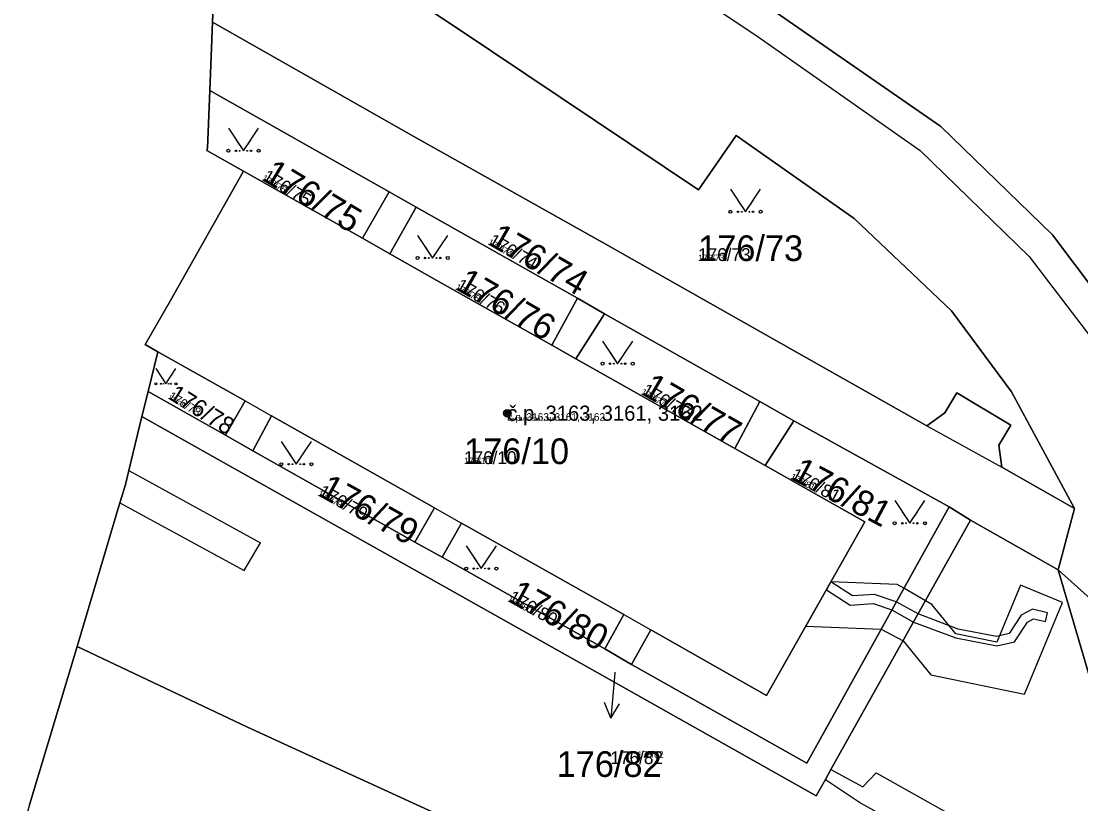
# Model space of a CAD drawing. Extents: x -759873 to -758487, y -975024 to -973516.
# Drawn here: x -759794.5 to -759724.3, y -974881.1 to -974829.3 of the extents above; entities that cross this region are included whole.
import ezdxf

# ---------------------------------------------------------------- set-up
doc = ezdxf.new("R2010")
doc.units = 0
for name, color, linetype in [('KAT_01_hranice KU', 7, 'Continuous'), ('KAT_02_hranice parcel', 7, 'Continuous'), ('KAT_03_1000_st čísla parcelní', 7, 'Continuous'), ('KAT_03_1000_čísla parcelní', 7, 'Continuous'), ('KAT_03_1000_čísla popisná', 7, 'Continuous'), ('KAT_03_250_st čísla parcelní', 7, 'Continuous'), ('KAT_03_250_čísla parcelní', 7, 'Continuous'), ('KAT_03_250_čísla popisná', 7, 'Continuous'), ('KAT_03_500_st čísla parcelní', 7, 'Continuous'), ('KAT_03_500_čísla parcelní', 7, 'Continuous'), ('KAT_03_500_čísla popisná', 7, 'Continuous'), ('KAT_04_vnitřní kresba', 7, 'Continuous'), ('KAT_05_1000_značky kultur', 7, 'Continuous'), ('KAT_05_250_značky kultur', 7, 'Continuous'), ('KAT_05_500_značky kultur', 7, 'Continuous'), ('KAT_07_1000_značky budov', 7, 'Continuous'), ('KAT_07_250_značky budov', 7, 'Continuous'), ('KAT_07_500_značky budov', 7, 'Continuous'), ('KAT_10_věcná břemena', 7, 'Continuous'), ('KAT_12_pomocná šipka', 7, 'Continuous'), ('KAT_14_plocha_budovy', 7, 'Continuous'), ('KAT_14_plocha_pozemek', 7, 'Continuous')]:
    doc.layers.add(name, color=color, linetype=linetype)

msp = doc.modelspace()

# ---------------------------------------------------------------- linework, layer by layer
at = {"layer": 'KAT_01_hranice KU'}
msp.add_lwpolyline([(-759781.42, -974819.34), (-759781.82, -974829.36), (-759782, -974833.89), (-759782.16, -974837.71), (-759782.2, -974837.87), (-759779.77, -974839.24), (-759784.62, -974847.8), (-759786.28, -974850.73), (-759785.45, -974851.2), (-759786.09, -974853.83), (-759786.5, -974855.48), (-759787.37, -974859.06), (-759787.62, -974860.09), (-759787.96, -974861.21), (-759790.8, -974870.73), (-759793.94, -974881.22)], dxfattribs=at)
at = {"layer": 'KAT_02_hranice parcel'}
for p, q in [((-759781.82, -974829.36), (-759781.42, -974819.34)), ((-759782, -974833.89), (-759781.82, -974829.36)), ((-759782, -974833.89), (-759770.13, -974840.61)), ((-759779.77, -974839.24), (-759782.2, -974837.87)), ((-759768.35, -974841.63), (-759770.13, -974840.61)), ((-759768.35, -974841.63), (-759757.65, -974847.65)), ((-759755.88, -974848.68), (-759757.65, -974847.65)), ((-759755.88, -974848.68), (-759745.58, -974854.5)), ((-759785.45, -974851.2), (-759786.28, -974850.73)), ((-759786.09, -974853.83), (-759785.45, -974851.2)), ((-759786.5, -974855.48), (-759786.09, -974853.83)), ((-759786.09, -974853.83), (-759780.96, -974856.72)), ((-759743.32, -974855.78), (-759745.58, -974854.5)), ((-759743.32, -974855.78), (-759733.05, -974861.48)), ((-759780.96, -974856.72), (-759779.17, -974857.76)), ((-759779.17, -974857.76), (-759768.43, -974863.81)), ((-759790.8, -974870.73), (-759787.96, -974861.21)), ((-759733.05, -974861.48), (-759731.62, -974862.36)), ((-759725.83, -974865.65), (-759724.75, -974861.59)), ((-759731.62, -974862.36), (-759725.83, -974865.65)), ((-759768.43, -974863.81), (-759766.63, -974864.81)), ((-759766.63, -974864.81), (-759755.84, -974870.88)), ((-759793.94, -974881.22), (-759790.8, -974870.73)), ((-759755.84, -974870.88), (-759754.08, -974871.91))]:
    msp.add_line(p, q, dxfattribs=at)
for points in [[(-759724.75, -974861.59), (-759728.92, -974853.85), (-759732.89, -974848.49), (-759739.33, -974842.38), (-759747.14, -974836.88), (-759749.64, -974840.47), (-759765.62, -974829.77), (-759781.42, -974819.34)], [(-759720.36, -974851.23), (-759726.2, -974843.46), (-759733.59, -974836.28), (-759747.09, -974826.92)], [(-759781.82, -974829.36), (-759768.49, -974836.95), (-759755.87, -974844.03), (-759743.5, -974851.03), (-759734.53, -974856.1), (-759733.33, -974855.25), (-759732.53, -974853.92), (-759728.96, -974856.06), (-759729.76, -974857.39), (-759729.55, -974858.85), (-759724.75, -974861.59)], [(-759782.2, -974837.87), (-759782.16, -974837.71), (-759782, -974833.89)], [(-759786.28, -974850.73), (-759784.62, -974847.8), (-759779.77, -974839.24)], [(-759770.13, -974840.61), (-759771.9, -974843.68), (-759779.77, -974839.24)], [(-759757.65, -974847.65), (-759759.35, -974850.77), (-759766.97, -974846.48), (-759770.08, -974844.71), (-759768.35, -974841.63)], [(-759745.58, -974854.5), (-759747.24, -974857.61), (-759754.44, -974853.55), (-759757.77, -974851.66), (-759755.88, -974848.68)], [(-759785.45, -974851.2), (-759779.66, -974854.46), (-759780.96, -974856.72)], [(-759787.96, -974861.21), (-759787.62, -974860.09), (-759787.37, -974859.06), (-759786.5, -974855.48)], [(-759786.5, -974855.48), (-759781.8, -974858.13), (-759756.7, -974872.25), (-759741.85, -974880.62), (-759741.24, -974879.53), (-759740.87, -974878.88), (-759731.62, -974862.36)], [(-759779.17, -974857.76), (-759777.92, -974855.45), (-759767.13, -974861.54), (-759768.43, -974863.81)], [(-759754.08, -974871.91), (-759752.8, -974869.63), (-759745.13, -974873.96), (-759738.62, -974862.47), (-759745.23, -974858.74), (-759743.32, -974855.78)], [(-759754.08, -974871.91), (-759742.48, -974878.45), (-759733.05, -974861.48)], [(-759766.63, -974864.81), (-759765.33, -974862.56), (-759754.6, -974868.61), (-759755.84, -974870.88)], [(-759726.65, -974903.86), (-759722.01, -974906.18), (-759718.12, -974905.68), (-759715.36, -974903.46), (-759715.21, -974901.51), (-759717.33, -974894.35), (-759721.59, -974880.08), (-759725.83, -974865.65)], [(-759790.8, -974870.73), (-759779.51, -974876.07), (-759763.52, -974883.39), (-759745.63, -974891.96), (-759725.52, -974901.55), (-759726.65, -974903.86)]]:
    msp.add_lwpolyline(points, dxfattribs=at)
at = {"layer": 'KAT_03_1000_čísla popisná'}
msp.add_circle((-759762.3, -974855.27), 0.25, dxfattribs=at)
at = {"layer": 'KAT_03_250_čísla popisná'}
msp.add_circle((-759762.3, -974855.27), 0.0625, dxfattribs=at)
at = {"layer": 'KAT_03_500_čísla popisná'}
msp.add_circle((-759762.3, -974855.27), 0.125, dxfattribs=at)
at = {"layer": 'KAT_04_vnitřní kresba'}
for p, q in [((-759759.54, -974821.08), (-759745.85, -974830.23)), ((-759745.85, -974830.23), (-759734.96, -974837.86)), ((-759734.96, -974837.86), (-759727.75, -974844.9)), ((-759771.9, -974843.68), (-759770.08, -974844.71)), ((-759727.75, -974844.9), (-759723.04, -974851.05)), ((-759759.35, -974850.77), (-759757.77, -974851.66)), ((-759779.66, -974854.46), (-759777.92, -974855.45)), ((-759734.53, -974856.1), (-759729.55, -974858.85)), ((-759747.24, -974857.61), (-759745.23, -974858.74)), ((-759787.37, -974859.06), (-759778.66, -974863.85)), ((-759787.96, -974861.21), (-759779.74, -974865.7)), ((-759767.13, -974861.54), (-759765.33, -974862.56)), ((-759779.74, -974865.7), (-759778.66, -974863.85)), ((-759725.83, -974865.65), (-759723.69, -974867.57)), ((-759754.6, -974868.61), (-759752.8, -974869.63)), ((-759740.87, -974878.88), (-759738.75, -974880.03)), ((-759737.88, -974879.09), (-759738.75, -974880.03)), ((-759737.88, -974879.09), (-759729.98, -974883.52)), ((-759741.24, -974879.53), (-759738.86, -974881.13)), ((-759738.86, -974881.13), (-759731.02, -974885.44))]:
    msp.add_line(p, q, dxfattribs=at)
at = {"layer": 'KAT_05_1000_značky kultur'}
for points in [[(-759780.78, -974836.389), (-759779.78, -974837.89), (-759778.78, -974836.389)], [(-759747.53, -974840.429), (-759746.53, -974841.93), (-759745.53, -974840.429)], [(-759768.25, -974843.489), (-759767.25, -974844.99), (-759766.25, -974843.489)], [(-759756, -974850.489), (-759755, -974851.99), (-759754, -974850.489)], [(-759785.59, -974852.314), (-759784.92, -974853.32), (-759784.25, -974852.314)], [(-759777.28, -974857.149), (-759776.28, -974858.65), (-759775.28, -974857.149)], [(-759736.65, -974861.059), (-759735.65, -974862.56), (-759734.65, -974861.059)], [(-759765.03, -974864.059), (-759764.03, -974865.56), (-759763.03, -974864.059)]]:
    msp.add_lwpolyline(points, dxfattribs=at)
for centre, radius in [((-759780.78, -974837.889), 0.1), ((-759778.78, -974837.889), 0.1), ((-759747.53, -974841.929), 0.1), ((-759745.53, -974841.929), 0.1), ((-759768.25, -974844.989), 0.1), ((-759766.25, -974844.989), 0.1), ((-759756, -974851.989), 0.1), ((-759754, -974851.989), 0.1), ((-759785.59, -974853.32), 0.067), ((-759784.25, -974853.32), 0.067), ((-759777.28, -974858.649), 0.1), ((-759775.28, -974858.649), 0.1), ((-759736.65, -974862.559), 0.1), ((-759734.65, -974862.559), 0.1), ((-759765.03, -974865.559), 0.1), ((-759763.03, -974865.559), 0.1)]:
    msp.add_circle(centre, radius, dxfattribs=at)
at = {"layer": 'KAT_05_250_značky kultur'}
for points in [[(-759780.03, -974837.515), (-759779.78, -974837.89), (-759779.53, -974837.515)], [(-759746.78, -974841.555), (-759746.53, -974841.93), (-759746.28, -974841.555)], [(-759767.5, -974844.615), (-759767.25, -974844.99), (-759767, -974844.615)], [(-759755.25, -974851.615), (-759755, -974851.99), (-759754.75, -974851.615)], [(-759785.088, -974853.069), (-759784.92, -974853.32), (-759784.753, -974853.069)], [(-759776.53, -974858.275), (-759776.28, -974858.65), (-759776.03, -974858.275)], [(-759735.9, -974862.185), (-759735.65, -974862.56), (-759735.4, -974862.185)], [(-759764.28, -974865.185), (-759764.03, -974865.56), (-759763.78, -974865.185)]]:
    msp.add_lwpolyline(points, dxfattribs=at)
for centre, radius in [((-759780.03, -974837.89), 0.025), ((-759779.53, -974837.89), 0.025), ((-759746.78, -974841.93), 0.025), ((-759746.28, -974841.93), 0.025), ((-759767.5, -974844.99), 0.025), ((-759767, -974844.99), 0.025), ((-759755.25, -974851.99), 0.025), ((-759754.75, -974851.99), 0.025), ((-759785.088, -974853.32), 0.0168), ((-759784.753, -974853.32), 0.0168), ((-759776.53, -974858.65), 0.025), ((-759776.03, -974858.65), 0.025), ((-759735.9, -974862.56), 0.025), ((-759735.4, -974862.56), 0.025), ((-759764.28, -974865.56), 0.025), ((-759763.78, -974865.56), 0.025)]:
    msp.add_circle(centre, radius, dxfattribs=at)
at = {"layer": 'KAT_05_500_značky kultur'}
for points in [[(-759780.28, -974837.14), (-759779.78, -974837.89), (-759779.28, -974837.14)], [(-759747.03, -974841.179), (-759746.53, -974841.93), (-759746.03, -974841.179)], [(-759767.75, -974844.24), (-759767.25, -974844.99), (-759766.75, -974844.24)], [(-759755.5, -974851.24), (-759755, -974851.99), (-759754.5, -974851.24)], [(-759785.255, -974852.817), (-759784.92, -974853.32), (-759784.585, -974852.817)], [(-759776.78, -974857.9), (-759776.28, -974858.65), (-759775.78, -974857.9)], [(-759736.15, -974861.809), (-759735.65, -974862.56), (-759735.15, -974861.809)], [(-759764.53, -974864.809), (-759764.03, -974865.56), (-759763.53, -974864.809)]]:
    msp.add_lwpolyline(points, dxfattribs=at)
for centre, radius in [((-759780.28, -974837.89), 0.05), ((-759779.28, -974837.89), 0.05), ((-759747.03, -974841.93), 0.05), ((-759746.03, -974841.93), 0.05), ((-759767.75, -974844.99), 0.05), ((-759766.75, -974844.99), 0.05), ((-759755.5, -974851.99), 0.05), ((-759754.5, -974851.99), 0.05), ((-759785.255, -974853.32), 0.0335), ((-759784.585, -974853.32), 0.0335), ((-759776.78, -974858.65), 0.05), ((-759775.78, -974858.65), 0.05), ((-759736.15, -974862.56), 0.05), ((-759735.15, -974862.56), 0.05), ((-759764.53, -974865.56), 0.05), ((-759763.53, -974865.56), 0.05)]:
    msp.add_circle(centre, radius, dxfattribs=at)
at = {"layer": 'KAT_07_1000_značky budov'}
msp.add_circle((-759762.307, -974855.269), 0.175, dxfattribs=at)
at = {"layer": 'KAT_07_250_značky budov'}
msp.add_circle((-759762.302, -974855.27), 0.0437, dxfattribs=at)
at = {"layer": 'KAT_07_500_značky budov'}
msp.add_circle((-759762.303, -974855.27), 0.0875, dxfattribs=at)
at = {"layer": 'KAT_10_věcná břemena'}
for points in [[(-759740.87, -974866.44), (-759742.53, -974869.38), (-759737.54, -974869.57), (-759736.09, -974870.35), (-759734.25, -974872.6), (-759728.06, -974873.88), (-759725.54, -974867.82), (-759728.31, -974866.67), (-759729.88, -974870.44), (-759732.61, -974869.88), (-759734.19, -974867.94), (-759734.61, -974867.7), (-759736.04, -974866.86), (-759736.48, -974866.61)], [(-759740.87, -974866.45), (-759741.17, -974866.97), (-759739.61, -974867.98), (-759738.07, -974867.88), (-759736.84, -974868.3), (-759735.4, -974869.11), (-759732.61, -974870.15), (-759729.88, -974870.68), (-759728.72, -974870.41), (-759727.86, -974869.11), (-759727.45, -974868.9), (-759726.67, -974869.07), (-759726.53, -974868.49), (-759727.53, -974868.26), (-759728.28, -974868.65), (-759729.08, -974869.87), (-759729.9, -974870.06), (-759732.45, -974869.57), (-759735.09, -974868.56), (-759736.55, -974867.77), (-759737.99, -974867.28), (-759739.45, -974867.36)]]:
    msp.add_lwpolyline(points, close=True, dxfattribs=at)
at = {"layer": 'KAT_12_pomocná šipka'}
for p, q in [((-759755.19, -974872.49), (-759755.452, -974875.48)), ((-759755.18, -974872.42), (-759755.19, -974872.49)), ((-759755.452, -974875.48), (-759755.863, -974874.438)), ((-759755.452, -974875.48), (-759754.865, -974874.526))]:
    msp.add_line(p, q, dxfattribs=at)
at = {"layer": 'KAT_14_plocha_budovy'}
msp.add_lwpolyline([(-759765.33, -974862.56), (-759754.6, -974868.61), (-759752.8, -974869.63), (-759745.13, -974873.96), (-759738.62, -974862.47), (-759745.23, -974858.74), (-759747.24, -974857.61), (-759754.44, -974853.55), (-759757.77, -974851.66), (-759759.35, -974850.77), (-759766.97, -974846.48), (-759770.08, -974844.71), (-759771.9, -974843.68), (-759779.77, -974839.24), (-759784.62, -974847.8), (-759786.28, -974850.73), (-759785.45, -974851.2), (-759779.66, -974854.46), (-759777.92, -974855.45), (-759767.13, -974861.54)], close=True, dxfattribs=at)
at = {"layer": 'KAT_14_plocha_pozemek'}
for points in [[(-759779.06, -974769.72), (-759779.44, -974777.04), (-759772.97, -974781.39), (-759761.49, -974788.95), (-759760.72, -974789.46), (-759745.11, -974799.84), (-759733.13, -974807.82), (-759734.33, -974809.6), (-759736.06, -974812.44), (-759729.75, -974816.63), (-759737.09, -974827.63), (-759744.46, -974822.74), (-759747.09, -974826.92), (-759733.59, -974836.28), (-759726.2, -974843.46), (-759720.36, -974851.23), (-759711.23, -974851.62), (-759701.47, -974851.98), (-759697.34, -974852.13), (-759694.68, -974852.23), (-759679.76, -974852.8), (-759656.08, -974853.68)], [(-759720.36, -974851.23), (-759726.2, -974843.46), (-759733.59, -974836.28), (-759747.09, -974826.92), (-759748.83, -974825.72), (-759759.14, -974818.84), (-759760.89, -974817.68), (-759771.13, -974810.81), (-759773.46, -974808.85), (-759780.78, -974804.2), (-759780.89, -974806.87), (-759781.42, -974819.34), (-759765.62, -974829.77), (-759749.64, -974840.47), (-759747.14, -974836.88), (-759739.33, -974842.38), (-759732.89, -974848.49), (-759728.92, -974853.85), (-759724.75, -974861.59), (-759725.83, -974865.65), (-759721.59, -974880.08)]]:
    msp.add_lwpolyline(points, dxfattribs=at)
for points in [[(-759765.62, -974829.77), (-759781.42, -974819.34), (-759781.82, -974829.36), (-759768.49, -974836.95), (-759755.87, -974844.03), (-759743.5, -974851.03), (-759734.53, -974856.1), (-759733.33, -974855.25), (-759732.53, -974853.92), (-759728.96, -974856.06), (-759729.76, -974857.39), (-759729.55, -974858.85), (-759724.75, -974861.59), (-759728.92, -974853.85), (-759732.89, -974848.49), (-759739.33, -974842.38), (-759747.14, -974836.88), (-759749.64, -974840.47)], [(-759724.75, -974861.59), (-759729.55, -974858.85), (-759729.76, -974857.39), (-759728.96, -974856.06), (-759732.53, -974853.92), (-759733.33, -974855.25), (-759734.53, -974856.1), (-759743.5, -974851.03), (-759755.87, -974844.03), (-759768.49, -974836.95), (-759781.82, -974829.36), (-759782, -974833.89), (-759770.13, -974840.61), (-759768.35, -974841.63), (-759757.65, -974847.65), (-759755.88, -974848.68), (-759745.58, -974854.5), (-759743.32, -974855.78), (-759733.05, -974861.48), (-759731.62, -974862.36), (-759725.83, -974865.65)], [(-759779.77, -974839.24), (-759771.9, -974843.68), (-759770.13, -974840.61), (-759782, -974833.89), (-759782.16, -974837.71), (-759782.2, -974837.87)], [(-759757.65, -974847.65), (-759759.35, -974850.77), (-759766.97, -974846.48), (-759770.08, -974844.71), (-759768.35, -974841.63), (-759770.13, -974840.61), (-759771.9, -974843.68), (-759779.77, -974839.24), (-759784.62, -974847.8), (-759786.28, -974850.73), (-759785.45, -974851.2), (-759779.66, -974854.46), (-759780.96, -974856.72), (-759779.17, -974857.76), (-759777.92, -974855.45), (-759767.13, -974861.54), (-759768.43, -974863.81), (-759766.63, -974864.81), (-759765.33, -974862.56), (-759754.6, -974868.61), (-759755.84, -974870.88), (-759754.08, -974871.91), (-759752.8, -974869.63), (-759745.13, -974873.96), (-759738.62, -974862.47), (-759745.23, -974858.74), (-759743.32, -974855.78), (-759745.58, -974854.5), (-759747.24, -974857.61), (-759754.44, -974853.55), (-759757.77, -974851.66), (-759755.88, -974848.68)], [(-759757.65, -974847.65), (-759768.35, -974841.63), (-759770.08, -974844.71), (-759766.97, -974846.48), (-759759.35, -974850.77)], [(-759745.58, -974854.5), (-759755.88, -974848.68), (-759757.77, -974851.66), (-759754.44, -974853.55), (-759747.24, -974857.61)], [(-759780.96, -974856.72), (-759779.66, -974854.46), (-759785.45, -974851.2), (-759786.09, -974853.83)], [(-759731.62, -974862.36), (-759733.05, -974861.48), (-759742.48, -974878.45), (-759754.08, -974871.91), (-759755.84, -974870.88), (-759766.63, -974864.81), (-759768.43, -974863.81), (-759779.17, -974857.76), (-759780.96, -974856.72), (-759786.09, -974853.83), (-759786.5, -974855.48), (-759781.8, -974858.13), (-759756.7, -974872.25), (-759741.85, -974880.62), (-759741.24, -974879.53), (-759740.87, -974878.88)], [(-759717.33, -974894.35), (-759721.59, -974880.08), (-759725.83, -974865.65), (-759731.62, -974862.36), (-759740.87, -974878.88), (-759741.24, -974879.53), (-759741.85, -974880.62), (-759756.7, -974872.25), (-759781.8, -974858.13), (-759786.5, -974855.48), (-759787.37, -974859.06), (-759787.62, -974860.09), (-759787.96, -974861.21), (-759790.8, -974870.73), (-759779.51, -974876.07), (-759763.52, -974883.39), (-759745.63, -974891.96), (-759725.52, -974901.55), (-759726.65, -974903.86), (-759722.01, -974906.18), (-759718.12, -974905.68), (-759715.36, -974903.46), (-759715.21, -974901.51)], [(-759768.43, -974863.81), (-759767.13, -974861.54), (-759777.92, -974855.45), (-759779.17, -974857.76)], [(-759733.05, -974861.48), (-759743.32, -974855.78), (-759745.23, -974858.74), (-759738.62, -974862.47), (-759745.13, -974873.96), (-759752.8, -974869.63), (-759754.08, -974871.91), (-759742.48, -974878.45)], [(-759755.84, -974870.88), (-759754.6, -974868.61), (-759765.33, -974862.56), (-759766.63, -974864.81)], [(-759746.31, -974905.83), (-759744.09, -974906.93), (-759733.22, -974912.08), (-759730.98, -974913.14), (-759730.24, -974911.42), (-759727.65, -974905.73), (-759726.65, -974903.86), (-759725.52, -974901.55), (-759745.63, -974891.96), (-759763.52, -974883.39), (-759779.51, -974876.07), (-759790.8, -974870.73), (-759793.94, -974881.22), (-759794.5, -974883.08), (-759792.2, -974884.17), (-759789.96, -974885.26), (-759779.51, -974890.14), (-759777.19, -974891.18), (-759762.83, -974898.01), (-759760.56, -974899.05)]]:
    msp.add_lwpolyline(points, close=True, dxfattribs=at)

# ---------------------------------------------------------------- texts
at = {"layer": 'KAT_03_1000_st čísla parcelní'}
msp.add_text('176/10', height=1.7, dxfattribs=at).set_placement((-759765.17, -974858.64))
at = {"layer": 'KAT_03_1000_čísla parcelní'}
for s, height, rotation, p in [('176/75', 1.7, 329, (-759778.597, -974839.808)), ('176/74', 1.7, 330, (-759763.635, -974844.066)), ('176/76', 1.7, 330, (-759765.785, -974847.036)), ('176/77', 1.7, 330, (-759753.485, -974853.986)), ('176/78', 1.14, 328, (-759784.802, -974854.283)), ('176/81', 1.7, 332, (-759743.599, -974859.6)), ('176/79', 1.7, 331, (-759774.892, -974860.703)), ('176/80', 1.7, 331, (-759762.322, -974867.703))]:
    msp.add_text(s, height=height, rotation=rotation, dxfattribs=at).set_placement(p)
for s, p in [('176/73', (-759749.67, -974845.19)), ('176/82', (-759759.041, -974879.363))]:
    msp.add_text(s, height=1.7, dxfattribs=at).set_placement(p)
at = {"layer": 'KAT_03_1000_čísla popisná'}
msp.add_text('č.p. 3163, 3161, 3162', height=1, dxfattribs=at).set_placement((-759762.3, -974855.77))
at = {"layer": 'KAT_03_250_st čísla parcelní'}
msp.add_text('176/10', height=0.425, dxfattribs=at).set_placement((-759765.17, -974858.64))
at = {"layer": 'KAT_03_250_čísla parcelní'}
for s, height, rotation, p in [('176/75', 0.425, 329, (-759778.597, -974839.808)), ('176/74', 0.425, 330, (-759763.635, -974844.066)), ('176/76', 0.425, 330, (-759765.785, -974847.036)), ('176/78', 0.285, 328, (-759784.802, -974854.283)), ('176/77', 0.425, 330, (-759753.485, -974853.986)), ('176/81', 0.425, 332, (-759743.599, -974859.6)), ('176/79', 0.425, 331, (-759774.892, -974860.703)), ('176/80', 0.425, 331, (-759762.322, -974867.703))]:
    msp.add_text(s, height=height, rotation=rotation, dxfattribs=at).set_placement(p)
for s, p in [('176/73', (-759749.67, -974845.19)), ('176/82', (-759753.689, -974878.088))]:
    msp.add_text(s, height=0.425, dxfattribs=at).set_placement(p)
at = {"layer": 'KAT_03_250_čísla popisná'}
msp.add_text('č.p. 3163, 3161, 3162', height=0.25, dxfattribs=at).set_placement((-759762.3, -974855.77))
at = {"layer": 'KAT_03_500_st čísla parcelní'}
msp.add_text('176/10', height=0.85, dxfattribs=at).set_placement((-759765.17, -974858.64))
at = {"layer": 'KAT_03_500_čísla parcelní'}
for s, height, rotation, p in [('176/75', 0.85, 329, (-759778.597, -974839.808)), ('176/74', 0.85, 330, (-759763.635, -974844.066)), ('176/76', 0.85, 330, (-759765.785, -974847.036)), ('176/77', 0.85, 330, (-759753.485, -974853.986)), ('176/78', 0.57, 328, (-759784.802, -974854.283)), ('176/81', 0.85, 332, (-759743.599, -974859.6)), ('176/79', 0.85, 331, (-759774.892, -974860.703)), ('176/80', 0.85, 331, (-759762.322, -974867.703))]:
    msp.add_text(s, height=height, rotation=rotation, dxfattribs=at).set_placement(p)
for s, p in [('176/73', (-759749.67, -974845.19)), ('176/82', (-759755.473, -974878.513))]:
    msp.add_text(s, height=0.85, dxfattribs=at).set_placement(p)
at = {"layer": 'KAT_03_500_čísla popisná'}
msp.add_text('č.p. 3163, 3161, 3162', height=0.5, dxfattribs=at).set_placement((-759762.3, -974855.77))

doc.saveas('drawing.dxf')
